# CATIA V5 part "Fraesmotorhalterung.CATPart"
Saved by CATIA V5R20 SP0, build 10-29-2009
Part number: Fraesmotorhalterung
Bounding box of the stored display mesh (mm): x -30 to 30, y -40 to 33, z 0 to 20
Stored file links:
  C:\Users\Andi\Desktop\Offene Projekte\Plasmacutter\Z-Achse\Fraesmotorhalterung.CATPart
  C:\Program Files\Dassault Systemes\B20\win_b64\reffiles\standard\MetricThickPitch.txt
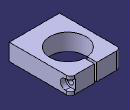
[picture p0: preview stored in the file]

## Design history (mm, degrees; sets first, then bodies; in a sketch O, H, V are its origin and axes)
Body1 (main body)
  Sketch1 on xy-plane, origin (0, 0, 0), H (1, 0, 0), V (0, 1, 0)
    line L1 (-25, 33) -> (-1.5, 33)
    line L2 (30, 28) -> (30, -40)
    line L3 (30, -40) -> (-30, -40)
    line L4 (-30, -40) -> (-30, 28)
    arc A1 centre (0, 0) radius 21.5 from (-1.5, 21.4476) to (1.5, 21.4476) ccw
    reference intersected line E1 through (0, 0) direction (-1, 0) from zx-plane
    line L5 (-1.5, 33) -> (-1.5, 21.4476)
    line L6 (1.5, 21.4476) -> (1.5, 33)
    point P5 (1.5, 33)
    line L7 (1.5, 33) -> (25, 33)
    arc A2 centre (-25, 28) radius 5 from (-25, 33) to (-30, 28) ccw
    arc A3 centre (25, 28) radius 5 from (30, 28) to (25, 33) ccw
    radius A1 = 21.5
    distance L4 L2 = 60
    distance A1 L2 = 8.5 (reference)
    distance E1 L1 = 33
    distance L5 L6 = 3
    length L6 = 11.5524 (reference)
    distance H L3 = 40
    radius A2 = 5
    radius A3 = 5 {= Sketch1.radius(A2)}
    horizontal: L1 H, L3 H, L7 H
    vertical: L2 V, L4 V, L5 V, L6 V
    symmetry: L4 L2 V, L6 L5 V
    coincidence: P5 L1, L1 L7
    tangency: A2 L1, A2 L4, A3 L2, A3 L7
  Pad1: profile Sketch1, direction (0, 0, 1), length 20
  Sketch2 on face of Pad1 from Sketch1.L2, origin (30, 25.1068, 11.211), H (0, 1, 0), V (0, 0, 1)
    point P1 (1.8932, -1.211)
    reference projected line E1 (-75.1068, 8.789) -> (1.8932, 8.789) from edge [face of Pad1 from Sketch1.L2 | end face of Pad1]
    reference projected line E2 (-75.1068, -11.211) -> (1.8932, -11.211) from edge [start face of Pad1 | face of Pad1 from Sketch1.L2]
    reference intersected line E4 through (7.8932, 0) direction (0, -1) from face of Pad1 from Sketch1.L7
    distance E4 P1 = 6
    equidistance: E1 E2 P1
  Hole1: placed by Sketch2, at (30, 27, 10) direction (-1, 0, 0), diameter 6.5, through (limit type 6)
  Sketch3 on face of Pad1 from Sketch1.L2, origin (30, 0, 0), H (0, 1, 0), V (0, 0, 1)
    line L1 (33, 16) -> (27, 16)
    line L2 (27, 4) -> (33, 4)
    line L3 (33, 4) -> (33, 16)
    arc A1 centre (27, 10) radius 6 from (27, 16) to (27, 4) ccw
    reference projected arc E1 centre (27, 10) radius 3.25 from (27, 6.75) to (27, 13.25) ccw from edge [face of Pad1 from Sketch1.A3 | face of Hole1]
    reference intersected line E2 through (33, 0) direction (0, -1) from face of Pad1 from Sketch1.L7
    radius A1 = 6
    horizontal: L1 H, L2 H
    vertical: L3 V
    tangency: A1 L2, A1 L1
    concentricity: A1 E1
    coincidence: E2 L3
  Pocket1: profile Sketch3, direction (-1, 0, 0), length 6
  Sketch4 on face of Pad1 from Sketch1.L5, origin (-1.5, 25.5367, 8.8721), H (0, 1, 0), V (0, 0, 1)
    point P1 (1.4633, 1.1279)
    reference projected circle E1 centre (1.4633, 1.1279) radius 3.25 from edge [end face of Pocket1 | face of Hole1]
    concentricity: P1 E1
  Hole2: placed by Sketch4, at (-1.5, 27, 10) direction (-1, 0, 0), diameter 4.917, through (limit type 6), threaded "M6", thread diameter 6, thread depth 28.5058, pitch 1
  Sketch5 on face of Pad1 from Sketch1.L3, origin (-18.2941, -40, 12.4425), H (1, 0, 0), V (0, 0, 1)
    point P1 (-4.7059, -2.4425)
    reference projected line E1 (-9.2059, 7.5575) -> (45.7941, 7.5575) from edge [face of Pad1 from Sketch1.L3 | end face of Pad1]
    reference projected line E2 (-9.2059, -12.4425) -> (45.7941, -12.4425) from edge [start face of Pad1 | face of Pad1 from Sketch1.L3]
    reference intersected line E3 through (18.2941, 0) direction (0, 1) from yz-plane
    distance E3 P1 = 23
    equidistance: E1 E2 P1
  Hole3: placed by Sketch5, at (-23, -40, 10) direction (0, 1, 0), diameter 4.134, depth 15, V-bottom angle 120, threaded "M5", thread diameter 5, thread depth 12, pitch 0.8
  RectPattern1: of Hole3, direction 1 instances 2, spacing 46, along face of Pad1 from Sketch1.L3 reversed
